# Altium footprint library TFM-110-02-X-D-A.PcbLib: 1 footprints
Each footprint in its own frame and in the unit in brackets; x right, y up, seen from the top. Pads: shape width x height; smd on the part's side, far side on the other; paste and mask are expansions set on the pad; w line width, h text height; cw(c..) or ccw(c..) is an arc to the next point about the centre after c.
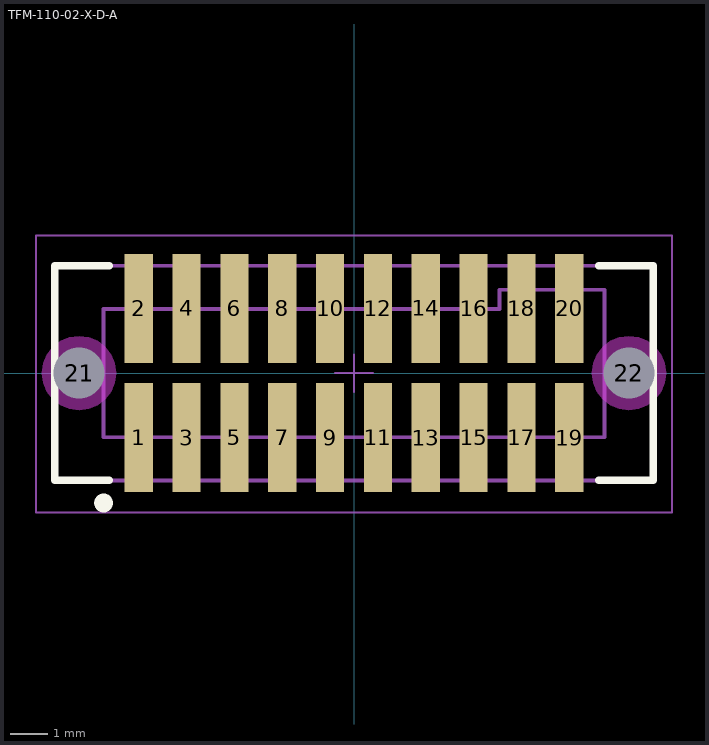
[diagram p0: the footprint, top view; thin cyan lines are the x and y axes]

## TFM-110-02-X-D-A [mm] "1.27mm pitch, 20 pin, terminal strip; w/alignment pins, SMT"
height 5.72
pads (22):
  rect 0.75x2.9 smd mask+0: 1(-5.715,-1.714) 2(-5.715,1.714) 3(-4.445,-1.714) 4(-4.445,1.714) 5(-3.175,-1.714) 6(-3.175,1.714) 7(-1.905,-1.714) 8(-1.905,1.714) 9(-0.635,-1.714) 10(-0.635,1.714) 11(0.635,-1.714) 12(0.635,1.714) 13(1.905,-1.714) 14(1.905,1.714) 15(3.175,-1.714) 16(3.175,1.714) 17(4.445,-1.714) 18(4.445,1.714) 19(5.715,-1.714) 20(5.715,1.714)
  round 1 hole 1.35 unplated mask+0: 21(-7.302,0) 22(7.302,0)
Top Overlay:
  circle w0.25: c-6.65,-3.45 r0.125
  lines w0.2: -6.5,-2.85 -7.95,-2.85 -7.95,2.85 -6.5,2.85 ; 6.5,-2.85 7.95,-2.85 7.95,2.85 6.5,2.85
Keep-Out Layer:
  pour cut-out: 8.286,0 8.253,0.255 8.154,0.492 7.998,0.695 7.794,0.852 7.557,0.95 7.303,0.983 7.048,0.95 6.811,0.852 6.607,0.695 6.451,0.492 6.353,0.255 6.319,0 6.353,-0.255 6.451,-0.492 6.607,-0.695 6.811,-0.852 7.048,-0.95 7.303,-0.983 7.557,-0.95 7.794,-0.852 7.998,-0.695 8.154,-0.492 8.253,-0.255
  pour cut-out: -6.319,0 -6.353,0.255 -6.451,0.492 -6.607,0.695 -6.811,0.852 -7.048,0.95 -7.303,0.983 -7.557,0.95 -7.794,0.852 -7.998,0.695 -8.154,0.492 -8.253,0.255 -8.286,0 -8.253,-0.255 -8.154,-0.492 -7.998,-0.695 -7.794,-0.852 -7.557,-0.95 -7.303,-0.983 -7.048,-0.95 -6.811,-0.852 -6.607,-0.695 -6.451,-0.492 -6.353,-0.255
Mechanical 12:
  lines w0.001: -7.95,-2.85 -7.95,2.85 7.95,2.85 7.95,-2.85 -7.95,-2.85
Mechanical 13:
  lines w0.1: -7.95,-2.85 -7.95,2.85 7.95,2.85 7.95,-2.85 -7.95,-2.85 ; -6.655,-1.702 -6.655,1.702 3.861,1.702 3.861,2.21 6.655,2.21 6.655,-1.702 -6.655,-1.702
  text ".Designator" at 0,-0.127 h1.52
Mechanical 15:
  lines w0.05: -0.5,0 0.5,0 ; 0,-0.5 0,0.5 ; -8.45,-3.7 -8.45,3.65 8.45,3.65 8.45,-3.7 -8.45,-3.7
